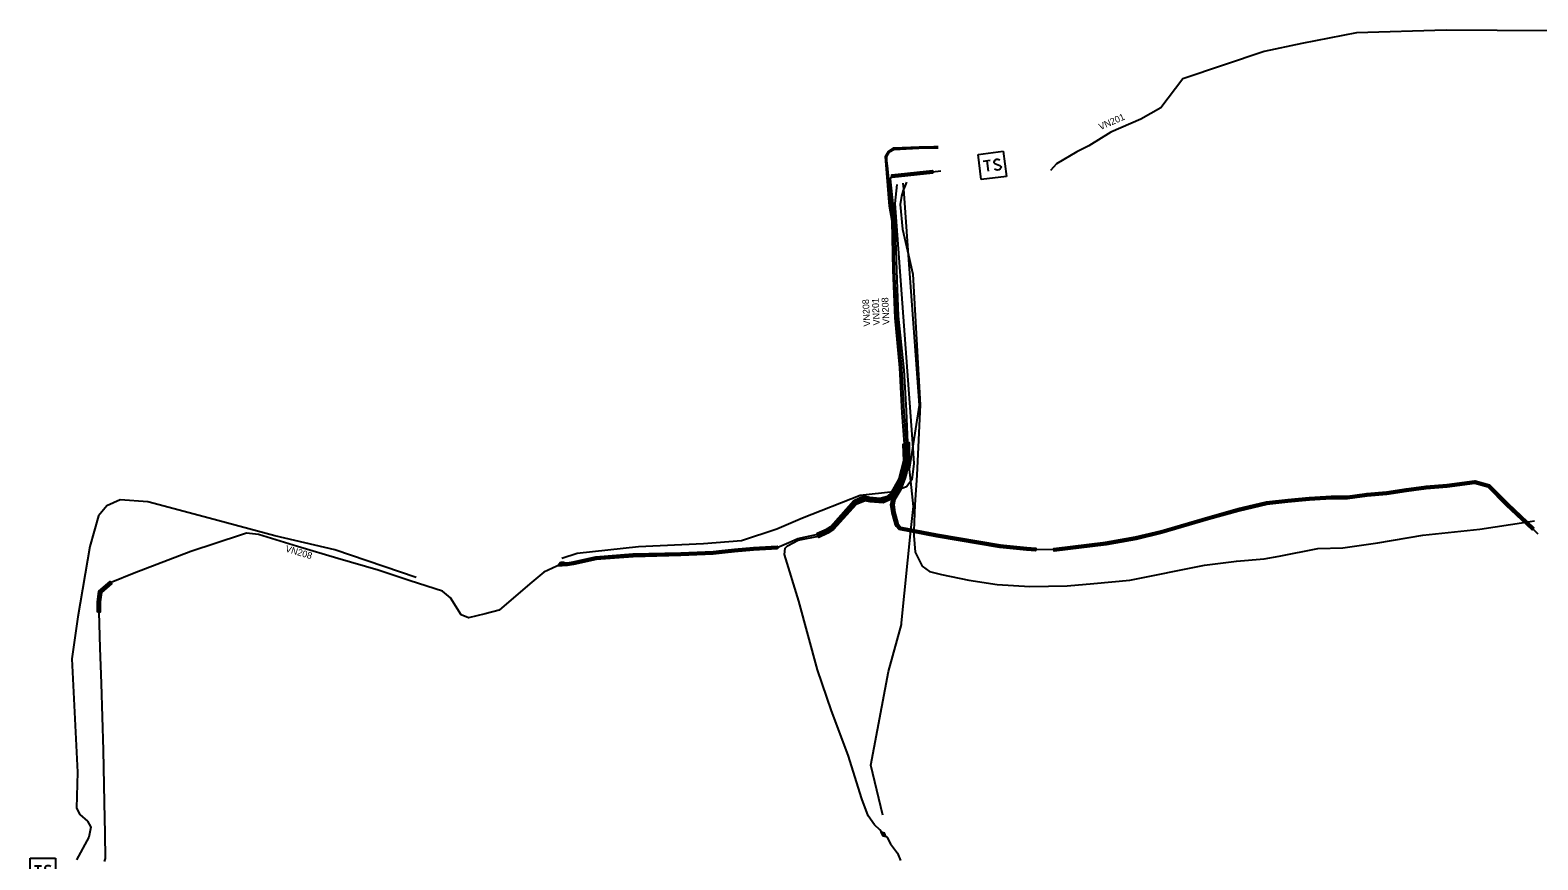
# Model space of a CAD drawing. Extents: x -643811 to -636362, y -1117362 to -1108614.
# Drawn here: x -641454.8 to -641230.5, y -1114397.7 to -1114274.2 of the extents above; entities that cross this region are included whole.
import ezdxf

# ---------------------------------------------------------------- set-up
doc = ezdxf.new("R2010")
doc.units = 0
for name, color, linetype in [('19', 7, 'Continuous'), ('20', 7, 'Continuous'), ('25', 7, 'Continuous'), ('5', 7, 'Continuous'), ('7', 7, 'Continuous'), ('9', 7, 'Continuous')]:
    doc.layers.add(name, color=color, linetype=linetype)

# ---------------------------------------------------------------- blocks, each defined once
blk = doc.blocks.new('VN870')
at = {"layer": '19'}
for points in [[(0, -0.25), (0.5, 0), (0, 0.25), (-0.5, 0), (0, -0.25)], [(0.37, 0), (0, 0.19), (-0.36, 0), (0, -0.19), (0.37, 0)], [(0.24, 0), (0, 0.12), (-0.25, 0), (0, -0.12), (0.24, 0)], [(0.12, 0), (0, 0.06), (-0.13, 0), (0, -0.06), (0.12, 0)]]:
    blk.add_lwpolyline(points, dxfattribs=at)
blk = doc.blocks.new('VN640')
at = {"layer": '25'}
for points in [[(-1.89, 1.89), (1.89, 1.89)], [(-1.89, -1.89), (-1.89, 1.89)], [(-1.26, 0.79), (-0.22, 0.79)], [(-0.73, 0.79), (-0.73, -0.79)], [(1.2, 0.66), (0.94, 0.79), (0.66, 0.79), (0.41, 0.66), (0.28, 0.47), (0.28, 0.41), (0.41, 0.22), (1.13, -0.16), (1.26, -0.32), (1.26, -0.47), (1.13, -0.66), (0.91, -0.79), (0.63, -0.79), (0.5, -0.73), (0.28, -0.6)], [(1.89, 1.89), (1.89, -1.89)], [(1.89, -1.89), (-1.89, -1.89)]]:
    blk.add_lwpolyline(points, dxfattribs=at)

msp = doc.modelspace()

# ---------------------------------------------------------------- linework, layer by layer
at = {"layer": '20'}
for points in [[(-641320.56, -1114295.5), (-641326.59, -1114296.13), (-641326.63, -1114295.73), (-641320.6, -1114295.1)], [(-641324.54, -1114335.77), (-641324.47, -1114338.32), (-641325.18, -1114341.11), (-641326.38, -1114343.24), (-641327.1, -1114343.89), (-641328.31, -1114344.24), (-641330.06, -1114344.11), (-641330.74, -1114343.9), (-641332.03, -1114344.51), (-641335.46, -1114348.38), (-641336.13, -1114348.83), (-641336.24, -1114348.66), (-641336.25, -1114348.64), (-641336.35, -1114348.49), (-641336.33, -1114348.48), (-641335.72, -1114348.08), (-641332.27, -1114344.19), (-641330.78, -1114343.48), (-641329.98, -1114343.71), (-641328.35, -1114343.84), (-641327.3, -1114343.53), (-641326.7, -1114342.98), (-641325.56, -1114340.95), (-641324.87, -1114338.28), (-641324.94, -1114335.79), (-641324.67, -1114335.78)], [(-641324.67, -1114335.78), (-641324.67, -1114335.71), (-641324.45, -1114335.71), (-641324.27, -1114335.71), (-641324.27, -1114338.29), (-641324.97, -1114341.14), (-641325.99, -1114343.1), (-641326.27, -1114343.39), (-641326.92, -1114344.08), (-641327.9, -1114344.52), (-641329.87, -1114344.39), (-641330.58, -1114344.23), (-641331.93, -1114344.8), (-641335.3, -1114348.53), (-641336.13, -1114349.03), (-641336.22, -1114348.87), (-641336.23, -1114348.86), (-641336.33, -1114348.69), (-641336.33, -1114348.68), (-641336.25, -1114348.64), (-641336.25, -1114348.64), (-641335.56, -1114348.21), (-641332.17, -1114344.46), (-641330.62, -1114343.81), (-641329.81, -1114343.99), (-641327.98, -1114344.12), (-641327.16, -1114343.74), (-641326.31, -1114342.86), (-641325.35, -1114341), (-641324.67, -1114338.25)], [(-641324.45, -1114335.71), (-641324.45, -1114335.58), (-641324.05, -1114335.58), (-641324.04, -1114338.4), (-641324.53, -1114340.58), (-641325.31, -1114342.56), (-641326.2, -1114344.06), (-641326.36, -1114344.86), (-641326.17, -1114345.97), (-641325.73, -1114347.63), (-641325.61, -1114347.82), (-641325.34, -1114348.14), (-641319.88, -1114349.18), (-641310.51, -1114350.78), (-641310.51, -1114350.78), (-641310.54, -1114350.98), (-641310.57, -1114351.18), (-641319.96, -1114349.58), (-641325.56, -1114348.5), (-641325.93, -1114348.06), (-641326.11, -1114347.79), (-641326.57, -1114346.05), (-641326.76, -1114344.86), (-641326.58, -1114343.92), (-641326.27, -1114343.39), (-641325.67, -1114342.38), (-641324.91, -1114340.46), (-641324.44, -1114338.36)], [(-641275.06, -1114345.59), (-641275.11, -1114345.4), (-641270.9, -1114344.38), (-641267.75, -1114344.03), (-641264.57, -1114343.76), (-641261.29, -1114343.54), (-641258.88, -1114343.53), (-641255.96, -1114343.14), (-641253.04, -1114342.88), (-641250.12, -1114342.45), (-641247.18, -1114342.06), (-641244.06, -1114341.81), (-641239.96, -1114341.27), (-641239.93, -1114341.47), (-641239.9, -1114341.67), (-641239.94, -1114341.67), (-641244.02, -1114342.21), (-641247.14, -1114342.46), (-641250.06, -1114342.85), (-641253, -1114343.28), (-641255.92, -1114343.54), (-641258.86, -1114343.93), (-641261.27, -1114343.94), (-641264.53, -1114344.16), (-641267.71, -1114344.43), (-641270.84, -1114344.78), (-641275.01, -1114345.78), (-641275.01, -1114345.78)], [(-641239.93, -1114341.47), (-641239.88, -1114341.28), (-641237.75, -1114341.87), (-641234.97, -1114344.65), (-641231.13, -1114348.27), (-641231.41, -1114348.57), (-641235.25, -1114344.93), (-641237.95, -1114342.23), (-641239.94, -1114341.67), (-641239.98, -1114341.66)], [(-641286.59, -1114348.68), (-641279.62, -1114346.65), (-641275.11, -1114345.4), (-641275.06, -1114345.59), (-641275.01, -1114345.78), (-641275.01, -1114345.78), (-641279.52, -1114347.03), (-641286.48, -1114349.06), (-641286.54, -1114348.87), (-641286.6, -1114348.68)], [(-641336.33, -1114348.48), (-641336.31, -1114348.47), (-641336.25, -1114348.64), (-641336.24, -1114348.66), (-641336.17, -1114348.85), (-641336.22, -1114348.87), (-641336.23, -1114348.87), (-641337.58, -1114349.41), (-641337.61, -1114349.31), (-641337.72, -1114349.03)], [(-641336.33, -1114348.68), (-641336.32, -1114348.68), (-641336.23, -1114348.86), (-641336.23, -1114348.87), (-641336.14, -1114349.04), (-641337.47, -1114349.69), (-641337.65, -1114349.33), (-641337.61, -1114349.31)], [(-641286.59, -1114348.68), (-641286.59, -1114348.68), (-641286.54, -1114348.87), (-641286.49, -1114349.06), (-641290.29, -1114350.01), (-641294.77, -1114350.79), (-641302.51, -1114351.73), (-641302.55, -1114351.33), (-641294.83, -1114350.39), (-641290.37, -1114349.61)], [(-641343.66, -1114351.4), (-641347.21, -1114351.58), (-641350.02, -1114351.84), (-641351.86, -1114352.03), (-641353.2, -1114352.16), (-641358.02, -1114352.39), (-641365.13, -1114352.55), (-641370.62, -1114352.99), (-641373.97, -1114353.72), (-641374.87, -1114353.87), (-641375.79, -1114353.84), (-641375.77, -1114353.46), (-641374.93, -1114353.47), (-641374.05, -1114353.32), (-641370.68, -1114352.59), (-641365.15, -1114352.15), (-641358.04, -1114351.99), (-641353.22, -1114351.76), (-641351.9, -1114351.63), (-641350.06, -1114351.44), (-641347.23, -1114351.18), (-641343.68, -1114351)], [(-641310.52, -1114350.78), (-641310.51, -1114350.78), (-641306.56, -1114351.2), (-641305.24, -1114351.26), (-641305.26, -1114351.66), (-641306.6, -1114351.6), (-641310.56, -1114351.18), (-641310.54, -1114350.98)], [(-641444.8, -1114360.8), (-641444.79, -1114359.25), (-641444.57, -1114357.68), (-641442.89, -1114356.24), (-641442.63, -1114356.54), (-641444.19, -1114357.88), (-641444.39, -1114359.27), (-641444.4, -1114360.8)]]:
    msp.add_lwpolyline(points, close=True, dxfattribs=at)
at = {"layer": '5'}
for points in [[(-641206.31, -1114274.47), (-641244.16, -1114274.22), (-641257.5, -1114274.6), (-641265.66, -1114276.19), (-641271.26, -1114277.4), (-641283.35, -1114281.48), (-641286.6, -1114285.78), (-641289.6, -1114287.46), (-641294.06, -1114289.42), (-641297.32, -1114291.44), (-641299.1, -1114292.33), (-641302.12, -1114294.12), (-641303.02, -1114295.12)], [(-641375.8, -1114353.65), (-641374.9, -1114353.67), (-641374.01, -1114353.52), (-641370.65, -1114352.79), (-641365.14, -1114352.35), (-641358.03, -1114352.19), (-641353.21, -1114351.96), (-641351.88, -1114351.83), (-641350.04, -1114351.64), (-641347.22, -1114351.38), (-641343.67, -1114351.2), (-641341.94, -1114350.43), (-641340.63, -1114349.85), (-641337.65, -1114349.22), (-641336.24, -1114348.66), (-641335.59, -1114348.23), (-641332.15, -1114344.35), (-641330.76, -1114343.69), (-641330.02, -1114343.91), (-641328.33, -1114344.04), (-641327.2, -1114343.71), (-641326.54, -1114343.11), (-641326.41, -1114342.88), (-641325.37, -1114341.03), (-641324.67, -1114338.3), (-641324.74, -1114335.78), (-641325.1, -1114331.17), (-641325.44, -1114324.47), (-641326.14, -1114317.03), (-641326.45, -1114309.91), (-641326.58, -1114302.66), (-641326.99, -1114300.41), (-641327.53, -1114293.68), (-641327.58, -1114293.02), (-641327.12, -1114292.26), (-641326.36, -1114291.75), (-641322.59, -1114291.58), (-641320.39, -1114291.53), (-641319.74, -1114291.51)], [(-641327.88, -1114393.86), (-641328.42, -1114393.2), (-641329.2, -1114392.43), (-641330.13, -1114391.08), (-641331.1, -1114388.59), (-641333.13, -1114382.1), (-641335.59, -1114375.5), (-641337.69, -1114369.38), (-641339.08, -1114364.28), (-641340.47, -1114359.18), (-641342.59, -1114352.22), (-641342.49, -1114351.29), (-641342.16, -1114350.95), (-641340.55, -1114350.09), (-641337.56, -1114349.51), (-641336.23, -1114348.86), (-641335.43, -1114348.37), (-641332.05, -1114344.63), (-641330.6, -1114344.02), (-641329.84, -1114344.19), (-641327.94, -1114344.32), (-641327.04, -1114343.91), (-641326.15, -1114342.98), (-641326.03, -1114342.75), (-641325.16, -1114341.07), (-641324.47, -1114338.27), (-641324.47, -1114335.71), (-641324.8, -1114330.98), (-641325.14, -1114324.57), (-641325.87, -1114316.95), (-641326.22, -1114309.88), (-641326.39, -1114302.56), (-641326.7, -1114300.41), (-641327.22, -1114294.86), (-641327.37, -1114293.6), (-641327.36, -1114293.02), (-641326.97, -1114292.34), (-641326.34, -1114291.95), (-641322.6, -1114291.78), (-641320.39, -1114291.73), (-641319.72, -1114291.71)], [(-641230.5, -1114349.22), (-641230.68, -1114348.98), (-641231.27, -1114348.42), (-641232.34, -1114347.41), (-641235.11, -1114344.79), (-641237.85, -1114342.05), (-641239.93, -1114341.47), (-641244.04, -1114342.01), (-641247.16, -1114342.26), (-641250.09, -1114342.65), (-641253.02, -1114343.08), (-641255.94, -1114343.34), (-641258.87, -1114343.73), (-641261.28, -1114343.74), (-641264.55, -1114343.96), (-641267.73, -1114344.23), (-641270.87, -1114344.58), (-641275.06, -1114345.59), (-641279.57, -1114346.84), (-641286.54, -1114348.87), (-641290.33, -1114349.81), (-641294.8, -1114350.59), (-641298.11, -1114350.97), (-641301.08, -1114351.37), (-641302.53, -1114351.53), (-641305.25, -1114351.46), (-641306.58, -1114351.4), (-641310.54, -1114350.98), (-641319.92, -1114349.38), (-641323.36, -1114348.72), (-641323.79, -1114348.64), (-641325.45, -1114348.32), (-641325.77, -1114347.94), (-641325.92, -1114347.71), (-641326.37, -1114346.01), (-641326.56, -1114344.86), (-641326.39, -1114343.99), (-641325.55, -1114342.57), (-641325.49, -1114342.47), (-641324.72, -1114340.52), (-641324.24, -1114338.38), (-641324.25, -1114335.58), (-641324.44, -1114330.81), (-641324.78, -1114324.81), (-641325.64, -1114316.76), (-641325.87, -1114310), (-641326.12, -1114302.39), (-641326.38, -1114300.49), (-641326.82, -1114296.36), (-641326.61, -1114295.93), (-641320.58, -1114295.3), (-641319.34, -1114295.16)], [(-641375.8, -1114353.65), (-641378.39, -1114354.87), (-641380.47, -1114356.61), (-641385.02, -1114360.52), (-641387.1, -1114361.07), (-641389.61, -1114361.65), (-641390.67, -1114361.21), (-641392.29, -1114358.66), (-641393.49, -1114357.68), (-641398.26, -1114356.12), (-641403.03, -1114354.57), (-641409.02, -1114352.82), (-641415.01, -1114351.06), (-641420.82, -1114349.24), (-641422.63, -1114349.07), (-641423.34, -1114349.28), (-641430.92, -1114351.79), (-641439.35, -1114355.02), (-641442.76, -1114356.39), (-641444.38, -1114357.78), (-641444.59, -1114359.26), (-641444.6, -1114360.8), (-641444.43, -1114366.11), (-641444.26, -1114371.42), (-641443.92, -1114381.31), (-641443.81, -1114389.13), (-641443.69, -1114393.73), (-641443.63, -1114397.46), (-641443.8, -1114397.91)], [(-641327.88, -1114393.86), (-641327.33, -1114394.35), (-641326.83, -1114395.26), (-641325.81, -1114396.67), (-641325.34, -1114397.73)]]:
    msp.add_lwpolyline(points, dxfattribs=at)
at = {"layer": '9'}
for points in [[(-641325.91, -1114297.18), (-641326.2, -1114300), (-641323.52, -1114336.42), (-641323.36, -1114338.68), (-641323.66, -1114341.11), (-641323.81, -1114341.31), (-641324.43, -1114342.14), (-641325.55, -1114342.57), (-641326.03, -1114342.75), (-641326.36, -1114342.87), (-641326.41, -1114342.88), (-641331.33, -1114343.47), (-641339.9, -1114346.82), (-641343.72, -1114348.48), (-641349.01, -1114350.21), (-641354.63, -1114350.66), (-641364.3, -1114351.1), (-641373.44, -1114352.06), (-641375.74, -1114352.84)], [(-641327.96, -1114390.98), (-641329.74, -1114383.56), (-641327.11, -1114369.65), (-641325.18, -1114362.62), (-641325.22, -1114362.39), (-641323.79, -1114348.64), (-641323.42, -1114345.09), (-641323.81, -1114341.31), (-641324, -1114339.53), (-641323.52, -1114336.42), (-641322.54, -1114329.99), (-641324.15, -1114307.7), (-641324.87, -1114297.81), (-641324.94, -1114296.96)], [(-641324.43, -1114296.83), (-641324.87, -1114297.81), (-641324.96, -1114298.01), (-641325.2, -1114298.9), (-641325.41, -1114300.15), (-641325.03, -1114303.81), (-641324.15, -1114307.7), (-641323.51, -1114310.54), (-641322.43, -1114329.97), (-641322.92, -1114340.43), (-641323.2, -1114344.84), (-641323.36, -1114348.72), (-641323.38, -1114349.4), (-641323.16, -1114351.88), (-641322.14, -1114353.98), (-641321.01, -1114354.76), (-641319.27, -1114355.2), (-641315.19, -1114356.04), (-641310.99, -1114356.69), (-641306.09, -1114356.99), (-641300.54, -1114356.87), (-641296.59, -1114356.56), (-641291.25, -1114356.04), (-641280.13, -1114353.83), (-641275.37, -1114353.2), (-641271.27, -1114352.85), (-641269, -1114352.47), (-641263.26, -1114351.35), (-641259.57, -1114351.21), (-641254.35, -1114350.47), (-641247.65, -1114349.34), (-641239.17, -1114348.45), (-641232.34, -1114347.41), (-641231.04, -1114347.22)], [(-641397.36, -1114355.64), (-641409.5, -1114351.53), (-641418.4, -1114349.47), (-641428.19, -1114346.81), (-641437.28, -1114344.4), (-641441.39, -1114344.11), (-641443.4, -1114345), (-641444.64, -1114346.45), (-641445.93, -1114351.06), (-641447.7, -1114361.5), (-641448.58, -1114367.73), (-641447.77, -1114384.63), (-641447.92, -1114389.97), (-641447.43, -1114390.93), (-641446.29, -1114391.9), (-641445.77, -1114392.8), (-641446.09, -1114394.29), (-641447.9, -1114397.64)]]:
    msp.add_lwpolyline(points, dxfattribs=at)

# ---------------------------------------------------------------- block references
at = {"layer": '19'}
for p, rotation in [((-641375.8, -1114353.65), -154), ((-641327.88, -1114393.86), -41.00000000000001)]:
    msp.add_blockref('VN870', p, dxfattribs=dict(at, rotation=rotation))
at = {"layer": '25', "rotation": 6.999999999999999}
msp.add_blockref('VN640', (-641311.7, -1114294.34), dxfattribs=at)
at = {"layer": '25'}
msp.add_blockref('VN640', (-641452.91, -1114399.31), dxfattribs=at)

# ---------------------------------------------------------------- texts
at = {"layer": '7'}
for s, rotation, p in [('VN201', 23.69, (-641295.6, -1114289.11)), ('VN208', 92.8341, (-641329.84, -1114318.28)), ('VN201', 92.8341, (-641328.41, -1114318.11)), ('VN208', 92.8341, (-641326.98, -1114318.02)), ('VN208', 343.626, (-641416.92, -1114351.79))]:
    msp.add_text(s, height=0.994, rotation=rotation, dxfattribs=at).set_placement(p)

doc.saveas('drawing.dxf')
